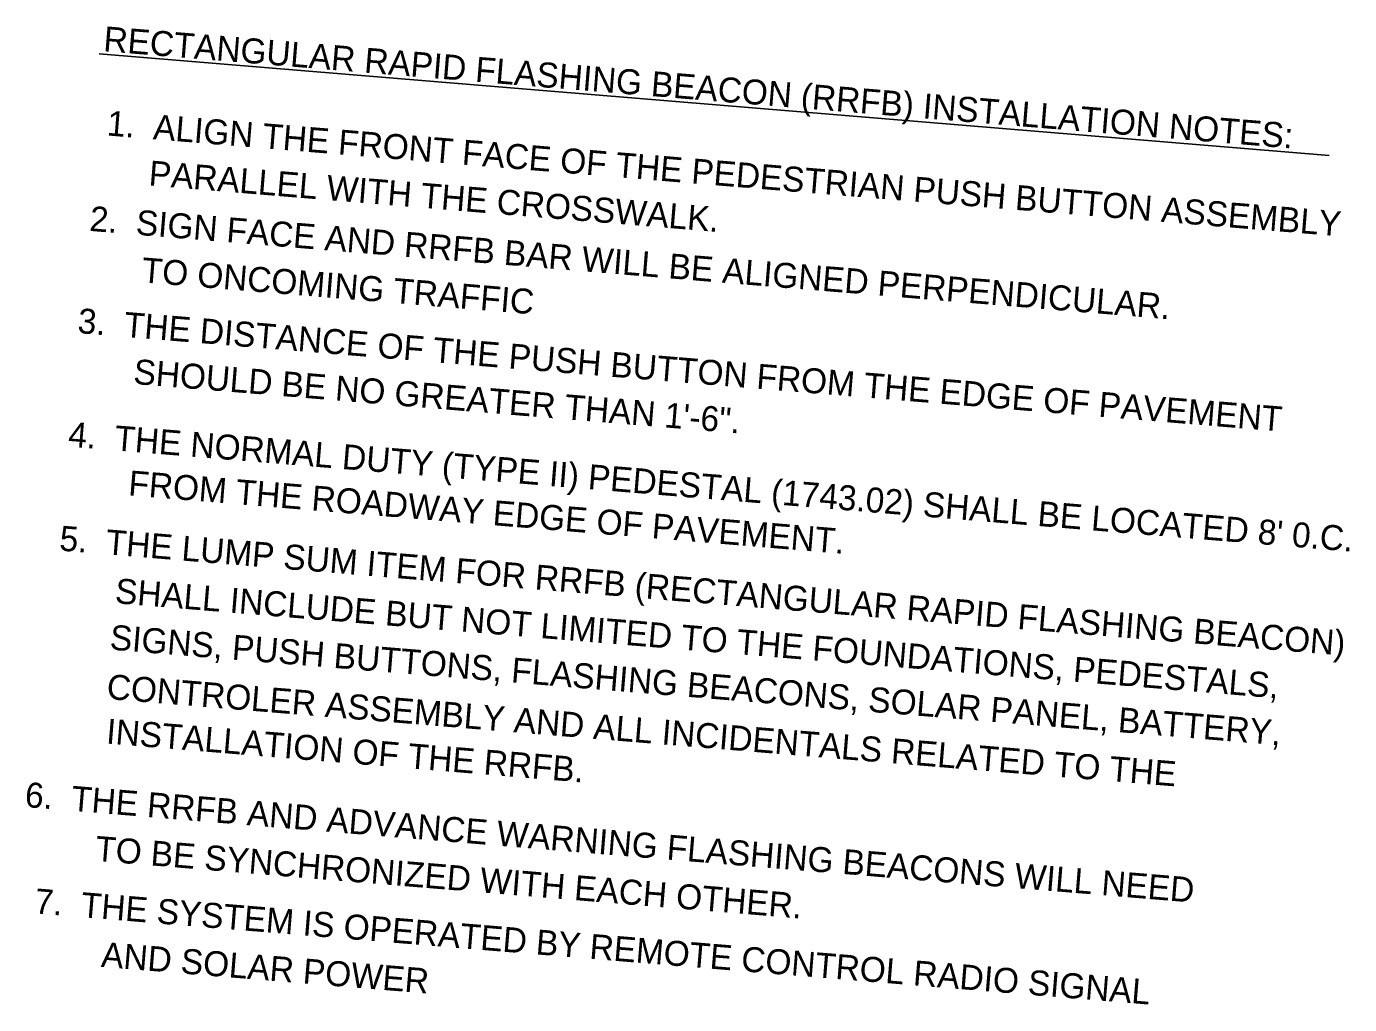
# Model space of a CAD drawing. Extents: x 902965 to 1126554, y 597041 to 686906.
# Drawn here: x 938242.4 to 938441.1, y 684050.6 to 684197.3 of the extents above; entities that cross this region are included whole.
import ezdxf

# ---------------------------------------------------------------- set-up
doc = ezdxf.new("R2010")
doc.units = 0
doc.layers.add('Default', color=7, linetype='Continuous')
doc.layers.add('Sheet Data Field CELL', color=7, linetype='Continuous')

msp = doc.modelspace()

# ---------------------------------------------------------------- linework, layer by layer
at = {"layer": 'Sheet Data Field CELL'}
msp.add_line((938253.35, 684193.23), (938438.01, 684177.96), dxfattribs=at)

# ---------------------------------------------------------------- texts
at = {"layer": 'Default'}
for s, p in [('RECTANGULAR RAPID FLASHING BEACON (RRFB) INSTALLATION NOTES:', (938253.91, 684193.64)), ('1.  ALIGN THE FRONT FACE OF THE PEDESTRIAN PUSH BUTTON ASSEMBLY ', (938254.43, 684181)), ('PARALLEL WITH THE CROSSWALK.', (938260.72, 684173.5)), ('2.  SIGN FACE AND RRFB BAR WILL BE ALIGNED PERPENDICULAR.', (938251.83, 684166.68)), ('TO ONCOMING TRAFFIC', (938259.65, 684158.96)), ('3.  THE DISTANCE OF THE PUSH BUTTON FROM THE EDGE OF PAVEMENT', (938250.04, 684151.35)), ('SHOULD BE NO GREATER THAN 1\'-6".', (938258.42, 684143.72)), ("4.  THE NORMAL DUTY (TYPE II) PEDESTAL (1743.02) SHALL BE LOCATED 8' 0.C. ", (938248.62, 684134.32)), ('FROM THE ROADWAY EDGE OF PAVEMENT.', (938257.66, 684127)), ('5.  THE LUMP SUM ITEM FOR RRFB (RECTANGULAR RAPID FLASHING BEACON)', (938247.31, 684118.72)), ('SHALL INCLUDE BUT NOT LIMITED TO THE FOUNDATIONS, PEDESTALS,', (938255.65, 684110.82)), ('SIGNS, PUSH BUTTONS, FLASHING BEACONS, SOLAR PANEL, BATTERY,', (938254.87, 684103.86)), ('CONTROLER ASSEMBLY AND ALL INCIDENTALS RELATED TO THE', (938254.4, 684096.45)), ('INSTALLATION OF THE RRFB.', (938254.34, 684089.76)), ('6.  THE RRFB AND ADVANCE WARNING FLASHING BEACONS WILL NEED', (938242.12, 684080.24)), ('TO BE SYNCHRONIZED WITH EACH OTHER.', (938252.67, 684072.16)), ('7.  THE SYSTEM IS OPERATED BY REMOTE CONTROL RADIO SIGNAL', (938243.57, 684064.28)), ('AND SOLAR POWER', (938253.57, 684056.25))]:
    msp.add_text(s, height=3.75, rotation=355.3222, dxfattribs=at).set_placement(p)

doc.saveas('drawing.dxf')
